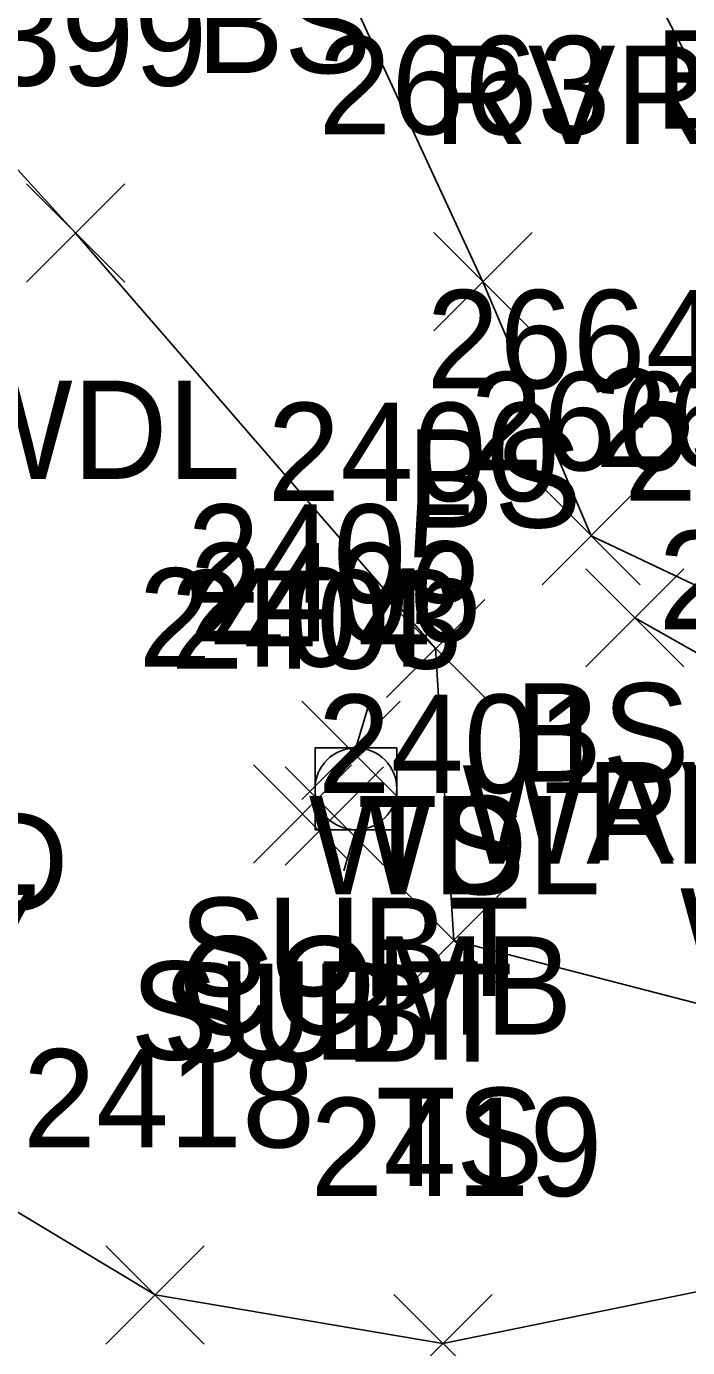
# Model space of a CAD drawing. Extents: x 1653135 to 1655489, y 602711 to 605684.
# Drawn here: x 1653718.91 to 1653732.38, y 605274.81 to 605301.69 of the extents above; entities that cross this region are included whole.
import ezdxf

# ---------------------------------------------------------------- set-up
doc = ezdxf.new("R2010")
doc.units = 0
for name, color, linetype in [('L_A', 7, 'Continuous'), ('L_I', 7, 'Continuous'), ('L_TIC', 7, 'Continuous'), ('LAWA', 7, 'Continuous'), ('LAWE', 7, 'Continuous'), ('LELB', 7, 'Continuous'), ('LW', 7, 'Continuous'), ('R_I', 7, 'Continuous'), ('R_TIC', 7, 'Continuous'), ('RGR', 7, 'Continuous'), ('U_A', 7, 'Continuous'), ('U_I', 7, 'Continuous'), ('U_TIC', 7, 'Continuous'), ('UP', 7, 'Continuous')]:
    doc.layers.add(name, color=color, linetype=linetype)

msp = doc.modelspace()

# ---------------------------------------------------------------- linework, layer by layer
at = {"layer": 'L_TIC'}
for points in [[(1653718.916, 605296.482), (1653720.916, 605298.482)], [(1653720.916, 605296.482), (1653718.916, 605298.482)], [(1653718.916, 605296.482), (1653720.916, 605298.482)], [(1653720.916, 605296.482), (1653718.916, 605298.482)], [(1653727.21, 605295.492), (1653729.21, 605297.492)], [(1653729.21, 605295.492), (1653727.21, 605297.492)], [(1653727.21, 605295.492), (1653729.21, 605297.492)], [(1653729.21, 605295.492), (1653727.21, 605297.492)], [(1653729.413, 605290.325), (1653731.413, 605292.325)], [(1653731.413, 605290.325), (1653729.413, 605292.325)], [(1653729.413, 605290.325), (1653731.413, 605292.325)], [(1653731.413, 605290.325), (1653729.413, 605292.325)], [(1653729.413, 605290.325), (1653731.413, 605292.325)], [(1653731.413, 605290.325), (1653729.413, 605292.325)], [(1653729.413, 605290.325), (1653731.413, 605292.325)], [(1653731.413, 605290.325), (1653729.413, 605292.325)], [(1653730.301, 605288.655), (1653732.301, 605290.655)], [(1653732.301, 605288.655), (1653730.301, 605290.655)], [(1653730.301, 605288.655), (1653732.301, 605290.655)], [(1653732.301, 605288.655), (1653730.301, 605290.655)], [(1653726.245, 605288.031), (1653728.245, 605290.031)], [(1653728.245, 605288.031), (1653726.245, 605290.031)], [(1653726.245, 605288.031), (1653728.245, 605290.031)], [(1653728.245, 605288.031), (1653726.245, 605290.031)], [(1653726.245, 605288.031), (1653728.245, 605290.031)], [(1653728.245, 605288.031), (1653726.245, 605290.031)], [(1653726.245, 605288.031), (1653728.245, 605290.031)], [(1653728.245, 605288.031), (1653726.245, 605290.031)], [(1653726.616, 605282.093), (1653728.616, 605284.093)], [(1653728.616, 605282.093), (1653726.616, 605284.093)], [(1653726.616, 605282.093), (1653728.616, 605284.093)], [(1653728.616, 605282.093), (1653726.616, 605284.093)]]:
    msp.add_lwpolyline(points, dxfattribs=at)
at = {"layer": 'LAWA'}
msp.add_lwpolyline([(1653692.976, 605320.073), (1653709.42, 605308.994), (1653719.916, 605297.482), (1653727.245, 605289.031)], dxfattribs=at)
at = {"layer": 'LAWE'}
msp.add_lwpolyline([(1653733.79, 605289.723), (1653736.619, 605292.952), (1653730.682, 605304.293), (1653723.568, 605320.315), (1653713.009, 605340.72)], dxfattribs=at)
at = {"layer": 'LELB'}
for points in [[(1653702.889, 605335.187), (1653715.609, 605317.861), (1653723.934, 605305.737), (1653728.21, 605296.492), (1653730.413, 605291.325)], [(1653733.79, 605289.723), (1653730.413, 605291.325)], [(1653727.245, 605289.031), (1653727.616, 605283.093), (1653736.433, 605280.814)]]:
    msp.add_lwpolyline(points, dxfattribs=at)
at = {"layer": 'LW'}
msp.add_lwpolyline([(1653731.301, 605289.655), (1653735.732, 605287.152)], dxfattribs=at)
at = {"layer": 'R_TIC'}
for points in [[(1653720.533, 605274.88), (1653722.533, 605276.88)], [(1653722.533, 605274.88), (1653720.533, 605276.88)], [(1653720.533, 605274.88), (1653722.533, 605276.88)], [(1653722.533, 605274.88), (1653720.533, 605276.88)], [(1653726.394, 605273.891), (1653728.394, 605275.891)], [(1653728.394, 605273.891), (1653726.394, 605275.891)], [(1653726.394, 605273.891), (1653728.394, 605275.891)], [(1653728.394, 605273.891), (1653726.394, 605275.891)]]:
    msp.add_lwpolyline(points, dxfattribs=at)
at = {"layer": 'RGR'}
msp.add_lwpolyline([(1653715.96, 605279.234), (1653721.533, 605275.88), (1653727.394, 605274.891), (1653741.217, 605277.707)], dxfattribs=at)
at = {"layer": 'U_TIC'}
for points in [[(1653724.524, 605285.962), (1653726.524, 605287.962)], [(1653726.524, 605285.962), (1653724.524, 605287.962)], [(1653724.524, 605285.962), (1653726.524, 605287.962)], [(1653726.524, 605285.962), (1653724.524, 605287.962)], [(1653723.536, 605284.664), (1653725.536, 605286.664)], [(1653725.536, 605284.664), (1653723.536, 605286.664)], [(1653723.536, 605284.664), (1653725.536, 605286.664)], [(1653725.536, 605284.664), (1653723.536, 605286.664)], [(1653724.184, 605284.622), (1653726.184, 605286.622)], [(1653726.184, 605284.622), (1653724.184, 605286.622)], [(1653724.184, 605284.622), (1653726.184, 605286.622)], [(1653726.184, 605284.622), (1653724.184, 605286.622)]]:
    msp.add_lwpolyline(points, dxfattribs=at)
at = {"layer": 'UP'}
for p, q in [((1653725.874, 605287.842), (1653725.624, 605287.008)), ((1653724.791, 605285.342), (1653724.791, 605287.008)), ((1653724.791, 605287.008), (1653726.457, 605287.008)), ((1653726.457, 605287.008), (1653726.457, 605285.342)), ((1653725.624, 605286.175), (1653725.624, 605286.175)), ((1653726.457, 605285.342), (1653724.791, 605285.342)), ((1653725.374, 605284.508), (1653725.624, 605285.342))]:
    msp.add_line(p, q, dxfattribs=at)
msp.add_circle((1653725.624, 605286.175), 0.833, dxfattribs=at)

# ---------------------------------------------------------------- texts
at = {"layer": 'L_A'}
for s, p in [('BS', (1653722.375, 605300.737)), ('BS', (1653722.375, 605300.737)), ('BS', (1653731.7, 605299.606)), ('BS', (1653731.7, 605299.606)), ('RVRR', (1653727.194, 605299.293)), ('RVRR', (1653727.194, 605299.293)), ('WDL', (1653717.333, 605292.482)), ('WDL', (1653717.333, 605292.482)), ('BS', (1653726.651, 605291.492)), ('BS', (1653726.651, 605291.492)), ('BS', (1653728.854, 605286.325)), ('BS', (1653728.854, 605286.325)), ('BS', (1653728.854, 605286.325)), ('BS', (1653728.854, 605286.325)), ('RVRR', (1653730.302, 605284.723)), ('RVRR', (1653730.302, 605284.723)), ('WALL', (1653727.789, 605284.655)), ('WALL', (1653727.789, 605284.655)), ('WDL', (1653724.662, 605284.031)), ('WDL', (1653724.662, 605284.031)), ('TS', (1653725.654, 605284.031)), ('TS', (1653725.654, 605284.031)), ('CONCPAD', (1653706.404, 605283.691)), ('CONCPAD', (1653706.404, 605283.691)), ('WALL', (1653732.22, 605282.152)), ('WALL', (1653732.22, 605282.152)), ('TS', (1653726.025, 605278.093)), ('TS', (1653726.025, 605278.093))]:
    msp.add_text(s, height=2, dxfattribs=at).set_placement(p)
at = {"layer": 'L_I'}
for s, p in [('2399', (1653716.648, 605300.482)), ('2399', (1653716.648, 605300.482)), ('2663', (1653724.856, 605299.492)), ('2663', (1653724.856, 605299.492)), ('2664', (1653727.058, 605294.325)), ('2664', (1653727.058, 605294.325)), ('2664', (1653727.058, 605294.325)), ('2664', (1653727.058, 605294.325)), ('2665', (1653727.947, 605292.655)), ('2665', (1653727.947, 605292.655)), ('2645', (1653730.483, 605292.723)), ('2645', (1653730.483, 605292.723)), ('2645', (1653730.483, 605292.723)), ('2645', (1653730.483, 605292.723)), ('2400', (1653723.82, 605292.031)), ('2400', (1653723.82, 605292.031)), ('2400', (1653723.82, 605292.031)), ('2400', (1653723.82, 605292.031)), ('2644', (1653731.079, 605292.04)), ('2644', (1653731.079, 605292.04)), ('2667', (1653731.78, 605289.423)), ('2667', (1653731.78, 605289.423)), ('2401', (1653724.844, 605286.093)), ('2401', (1653724.844, 605286.093))]:
    msp.add_text(s, height=2, dxfattribs=at).set_placement(p)
at = {"layer": 'R_I'}
for s, p in [('2417', (1653713.267, 605282.234)), ('2417', (1653713.267, 605282.234)), ('2418', (1653718.841, 605278.88)), ('2418', (1653718.841, 605278.88)), ('2419', (1653724.694, 605277.891)), ('2419', (1653724.694, 605277.891))]:
    msp.add_text(s, height=2, dxfattribs=at).set_placement(p)
at = {"layer": 'U_A'}
for s, p in [('SUBT', (1653722.02, 605281.962)), ('SUBT', (1653722.02, 605281.962)), ('COMB', (1653722.01, 605281.175)), ('SUBT', (1653721.032, 605280.664)), ('SUBT', (1653721.032, 605280.664)), ('SUBT', (1653721.68, 605280.622)), ('SUBT', (1653721.68, 605280.622))]:
    msp.add_text(s, height=2, dxfattribs=at).set_placement(p)
at = {"layer": 'U_I'}
for s, p in [('2405', (1653722.186, 605289.962)), ('2405', (1653722.186, 605289.962)), ('2406', (1653722.231, 605289.175)), ('2404', (1653721.197, 605288.664)), ('2404', (1653721.197, 605288.664)), ('2403', (1653721.846, 605288.622)), ('2403', (1653721.846, 605288.622))]:
    msp.add_text(s, height=2, dxfattribs=at).set_placement(p)

doc.saveas('drawing.dxf')
